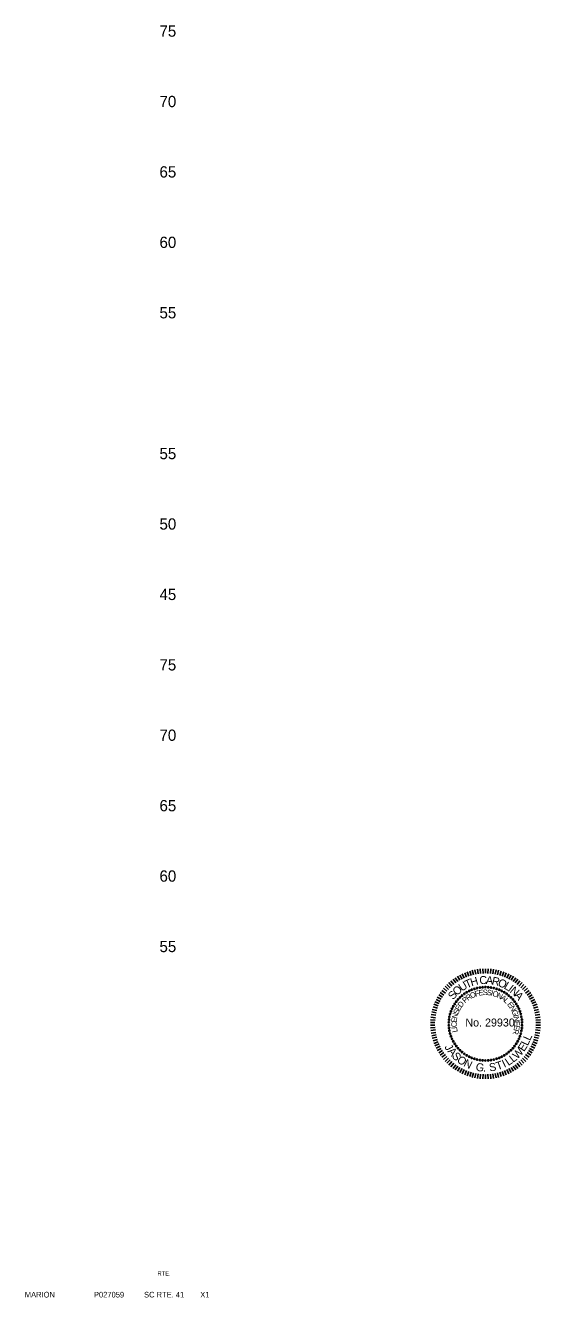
# Model space of a CAD drawing. Extents: x 952 to 1206, y 942 to 2399.
# Drawn here: x 1147.4 to 1184, y 1675.5 to 1765.8 of the extents above; entities that cross this region are included whole.
import ezdxf

# ---------------------------------------------------------------- set-up
doc = ezdxf.new("R2010")
doc.units = 0
for name, color, linetype in [('Default', 7, 'Continuous'), ('RD_SHT_TX', 7, 'Continuous'), ('RD_TX_PEShield', 7, 'Continuous'), ('RD_XS_TX_Elev_EX', 7, 'Continuous')]:
    doc.layers.add(name, color=color, linetype=linetype)

# ---------------------------------------------------------------- blocks, each defined once
blk = doc.blocks.new('STILLWELL')
at = {"layer": 'RD_TX_PEShield'}
for p, q in [((-10.28, 33.44), (-11.22, 36.57)), ((-8.61, 33.9), (-9.39, 37.07)), ((-6.92, 34.27), (-7.55, 37.48)), ((-5.21, 34.57), (-5.68, 37.8)), ((-3.49, 34.77), (-3.81, 38.03)), ((-1.76, 34.9), (-1.92, 38.16)), ((-0.03, 34.94), (-0.03, 38.21)), ((1.71, 34.9), (1.86, 38.16)), ((3.43, 34.77), (3.75, 38.03)), ((5.15, 34.57), (5.63, 37.8)), ((6.86, 34.27), (7.49, 37.48)), ((8.56, 33.9), (9.34, 37.07)), ((10.23, 33.44), (11.16, 36.57)), ((-23.81, 25.92), (-25.98, 28.37)), ((-22.49, 27.04), (-24.53, 29.59)), ((-21.11, 28.09), (-23.03, 30.73)), ((-19.68, 29.08), (-21.48, 31.81)), ((-18.21, 29.99), (-19.87, 32.81)), ((-16.7, 30.83), (-18.22, 33.73)), ((-15.14, 31.6), (-16.52, 34.56)), ((-13.55, 32.29), (-14.79, 35.32)), ((-11.93, 32.91), (-13.02, 35.99)), ((11.88, 32.91), (12.96, 35.99)), ((13.5, 32.29), (14.73, 35.32)), ((15.09, 31.6), (16.46, 34.56)), ((16.64, 30.83), (18.16, 33.73)), ((18.16, 29.99), (19.81, 32.81)), ((19.63, 29.08), (21.42, 31.81)), ((21.06, 28.09), (22.98, 30.73)), ((22.43, 27.04), (24.48, 29.59)), ((23.76, 25.92), (25.92, 28.37)), ((-31.38, 16.5), (-34.23, 18.09)), ((-30.5, 18), (-33.27, 19.72)), ((-29.55, 19.45), (-32.24, 21.3)), ((-28.53, 20.85), (-31.12, 22.83)), ((-27.44, 22.2), (-29.94, 24.31)), ((-26.29, 23.5), (-28.69, 25.72)), ((-25.08, 24.74), (-27.37, 27.08)), ((25.03, 24.74), (27.31, 27.08)), ((26.24, 23.5), (28.63, 25.72)), ((27.39, 22.2), (29.88, 24.31)), ((28.47, 20.85), (31.07, 22.83)), ((29.49, 19.45), (32.18, 21.3)), ((30.44, 18), (33.22, 19.72)), ((31.32, 16.5), (34.18, 18.09)), ((-34.64, 8.5), (-37.79, 9.35)), ((-34.14, 10.16), (-37.25, 11.17)), ((-33.57, 11.79), (-36.62, 12.95)), ((-32.91, 13.4), (-35.91, 14.7)), ((-32.18, 14.97), (-35.11, 16.42)), ((32.13, 14.97), (35.06, 16.42)), ((32.86, 13.4), (35.85, 14.7)), ((33.51, 11.79), (36.57, 12.95)), ((34.09, 10.16), (37.19, 11.17)), ((34.58, 8.5), (37.73, 9.35)), ((-35.89, -0.06), (-39.15, 0.02)), ((-35.8, 1.67), (-39.06, 1.91)), ((-35.64, 3.4), (-38.88, 3.79)), ((-35.39, 5.11), (-38.61, 5.66)), ((-35.05, 6.81), (-38.24, 7.52)), ((35, 6.81), (38.19, 7.52)), ((35.33, 5.11), (38.55, 5.66)), ((35.58, 3.4), (38.82, 3.79)), ((35.75, 1.67), (39.01, 1.91)), ((35.83, -0.06), (39.1, 0.02)), ((-35.89, -1.79), (-39.15, -1.87)), ((-35.8, -3.53), (-39.06, -3.76)), ((-35.64, -5.25), (-38.88, -5.65)), ((-35.39, -6.97), (-38.61, -7.52)), ((-35.05, -8.67), (-38.24, -9.37)), ((35, -8.67), (38.19, -9.37)), ((35.33, -6.97), (38.55, -7.52)), ((35.58, -5.25), (38.82, -5.65)), ((35.75, -3.53), (39.01, -3.76)), ((35.83, -1.79), (39.1, -1.87)), ((-34.64, -10.35), (-37.79, -11.21)), ((-34.14, -12.01), (-37.25, -13.02)), ((-33.57, -13.65), (-36.62, -14.81)), ((-32.91, -15.25), (-35.91, -16.56)), ((-32.18, -16.83), (-35.11, -18.27)), ((32.13, -16.83), (35.06, -18.27)), ((32.86, -15.25), (35.85, -16.56)), ((33.51, -13.65), (36.57, -14.81)), ((34.09, -12.01), (37.19, -13.02)), ((34.58, -10.35), (37.73, -11.21)), ((-31.38, -18.36), (-34.23, -19.95)), ((-30.5, -19.85), (-33.27, -21.58)), ((-29.55, -21.3), (-32.24, -23.16)), ((-28.53, -22.71), (-31.12, -24.69)), ((-27.44, -24.06), (-29.94, -26.16)), ((-26.29, -25.36), (-28.69, -27.58)), ((-25.08, -26.6), (-27.37, -28.93)), ((25.03, -26.6), (27.31, -28.93)), ((26.24, -25.36), (28.63, -27.58)), ((27.39, -24.06), (29.88, -26.16)), ((28.47, -22.71), (31.07, -24.69)), ((29.49, -21.3), (32.18, -23.16)), ((30.44, -19.85), (33.22, -21.58)), ((31.32, -18.36), (34.18, -19.95)), ((-23.81, -27.78), (-25.98, -30.22)), ((-22.49, -28.89), (-24.53, -31.44)), ((-21.11, -29.95), (-23.03, -32.59)), ((-19.68, -30.93), (-21.48, -33.66)), ((-18.21, -31.85), (-19.87, -34.66)), ((-16.7, -32.69), (-18.22, -35.58)), ((-15.14, -33.46), (-16.52, -36.42)), ((-13.55, -34.15), (-14.79, -37.18)), ((-11.93, -34.76), (-13.02, -37.85)), ((-10.28, -35.3), (-11.22, -38.43)), ((-8.61, -35.76), (-9.39, -38.93)), ((-6.92, -36.13), (-7.55, -39.34)), ((6.86, -36.13), (7.49, -39.34)), ((8.56, -35.76), (9.34, -38.93)), ((10.23, -35.3), (11.16, -38.43)), ((11.88, -34.76), (12.96, -37.85)), ((13.5, -34.15), (14.73, -37.18)), ((15.09, -33.46), (16.46, -36.42)), ((16.64, -32.69), (18.16, -35.58)), ((18.16, -31.85), (19.81, -34.66)), ((19.63, -30.93), (21.42, -33.66)), ((21.06, -29.95), (22.98, -32.59)), ((22.43, -28.89), (24.48, -31.44)), ((23.76, -27.78), (25.92, -30.22)), ((-5.21, -36.42), (-5.68, -39.65)), ((-3.49, -36.63), (-3.81, -39.88)), ((-1.76, -36.76), (-1.92, -40.02)), ((-0.03, -36.8), (-0.03, -40.06)), ((1.71, -36.76), (1.86, -40.02)), ((3.43, -36.63), (3.75, -39.88)), ((5.15, -36.42), (5.63, -39.65))]:
    blk.add_line(p, q, dxfattribs=at)
for centre in [(-18.09, 17.84), (-16.6, 19.17), (-15.01, 20.38), (-13.34, 21.46), (-11.59, 22.41), (-9.76, 23.23), (-7.89, 23.9), (-5.96, 24.43), (-4, 24.81), (-2.02, 25.04), (-0.03, 25.12), (1.97, 25.04), (3.95, 24.81), (5.91, 24.43), (7.83, 23.9), (9.71, 23.23), (11.53, 22.41), (13.28, 21.46), (14.96, 20.38), (16.54, 19.17), (18.03, 17.84), (-23.79, 9.73), (-22.91, 11.51), (-21.89, 13.23), (-20.74, 14.86), (-19.47, 16.4), (19.42, 16.4), (20.69, 14.86), (21.83, 13.23), (22.85, 11.51), (23.74, 9.73), (-26.05, 0.07), (-25.9, 2.06), (-25.6, 4.03), (-25.14, 5.97), (-24.54, 7.88), (24.48, 7.88), (25.09, 5.97), (25.54, 4.03), (25.85, 2.06), (26, 0.07), (-26.05, -1.93), (-25.9, -3.92), (-25.6, -5.89), (-25.14, -7.83), (25.09, -7.83), (25.54, -5.89), (25.85, -3.92), (26, -1.93), (-24.54, -9.73), (-23.79, -11.58), (-22.91, -13.37), (-21.89, -15.09), (-20.74, -16.72), (-19.47, -18.26), (19.42, -18.26), (20.69, -16.72), (21.83, -15.09), (22.85, -13.37), (23.74, -11.58), (24.48, -9.73), (-18.09, -19.69), (-16.6, -21.02), (-15.01, -22.23), (-13.34, -23.32), (-11.59, -24.27), (-9.76, -25.09), (-7.89, -25.76), (-5.96, -26.29), (-4, -26.67), (-2.02, -26.9), (-0.03, -26.97), (1.97, -26.9), (3.95, -26.67), (5.91, -26.29), (7.83, -25.76), (9.71, -25.09), (11.53, -24.27), (13.28, -23.32), (14.96, -22.23), (16.54, -21.02), (18.03, -19.69)]:
    blk.add_circle(centre, 0.49, dxfattribs=at)
for s, height, rotation, p in [('U', 5.68, 32.21524, (-16.89, 21.85)), ('T', 5.68, 23.50438, (-13.24, 24.14)), ('H', 5.68, 16.13567, (-9.92, 25.63)), ('C', 5.68, 4.07599, (-4.15, 27.11)), ('A', 5.68, 355.36513, (0.14, 27.41)), ('R', 5.68, 347.31877, (4.1, 27.11)), ('O', 5.68, 338.6079, (8.3, 26.16)), ('L', 5.68, 329.22596, (12.61, 24.44)), ('S', 5.68, 49.64355, (-22.94, 15.75)), ('O', 5.68, 41.59718, (-20.38, 18.79)), ('P', 3.92, 41.0022, (-14.52, 13.51)), ('R', 3.92, 33.30566, (-12.46, 15.32)), ('O', 3.92, 24.97351, (-9.98, 16.95)), ('F', 3.92, 15.99945, (-7.07, 18.28)), ('E', 3.92, 8.95111, (-4.65, 19)), ('S', 3.92, 1.25456, (-1.94, 19.44)), ('S', 3.92, 353.55802, (0.8, 19.51)), ('I', 3.92, 345.86148, (3.53, 19.22)), ('O', 3.92, 342.65826, (4.65, 18.99)), ('N', 3.92, 333.6842, (7.7, 18.01)), ('A', 3.92, 325.35205, (10.36, 16.69)), ('I', 5.68, 322.52176, (15.48, 22.79)), ('N', 5.68, 319.17294, (16.84, 21.84)), ('A', 5.68, 310.46208, (20.09, 19.02)), ('S', 3.92, 67.93066, (-19.49, 5.38)), ('E', 3.92, 60.23412, (-18.47, 7.93)), ('D', 3.92, 52.53758, (-17.12, 10.32)), ('L', 3.92, 317.65551, (12.63, 15.14)), ('E', 3.92, 308.03955, (15.14, 12.8)), ('N', 3.92, 300.34301, (16.84, 10.65)), ('C', 3.92, 92.29151, (-20.36, -3.21)), ('E', 3.92, 83.95936, (-20.47, -0.24)), ('N', 3.92, 76.26281, (-20.2, 2.49)), ('G', 3.92, 292.01086, (18.34, 8.08)), ('I', 3.92, 283.0368, (19.52, 5.11)), ('N', 3.92, 279.83358, (19.83, 4.01)), ('E', 3.92, 271.50143, (20.33, 1.08)), ('I', 3.92, 95.49473, (-20.2, -4.35)), ('L', 3.92, 101.90747, (-19.69, -6.58)), ('R', 3.92, 256.10834, (20.13, -4.4)), ('E', 3.92, 263.80489, (20.42, -1.67)), ('J', 5.68, 299.03302, (-29.35, -17.26)), ('W', 5.68, 47.05177, (22.62, -26.41)), ('E', 5.68, 56.4327, (27.3, -21.12)), ('L', 5.68, 65.09801, (29.98, -16.89)), ('L', 5.68, 65.09801, (31.58, -13.34)), ('A', 5.68, 310.58873, (-27.19, -20.61)), ('S', 5.68, 310.58873, (-24.3, -23.99)), ('O', 5.68, 321.00719, (-20.82, -27.39)), ('N', 5.68, 333.43256, (-16.05, -30.75)), ('T', 5.68, 18.90189, (8.5, -33.88)), ('I', 5.68, 25.39911, (13.3, -32.17)), ('L', 5.68, 34.06442, (16.21, -30.92)), ('L', 5.68, 37.67084, (19.57, -28.72)), ('G', 5.68, 352.2045, (-7.22, -34.2)), ('.', 5.68, 0.86982, (-1.8, -34.9)), ('S', 5.68, 8.08265, (2.93, -34.79))]:
    blk.add_text(s, height=height, rotation=rotation, dxfattribs=at).set_placement(p)
blk.add_text('No. 29930', height=5.685, dxfattribs=at).set_placement((-14.3, -2.84))

msp = doc.modelspace()

# ---------------------------------------------------------------- block references
at = {"layer": 'Default', "xscale": 0.1, "yscale": 0.10000000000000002}
msp.add_blockref('STILLWELL', (1180.075, 1695), dxfattribs=at)

# ---------------------------------------------------------------- texts
at = {"layer": 'RD_SHT_TX'}
for s, height, p in [('RTE.', 0.3, (1156.771, 1677.03)), ('MARION', 0.4, (1147.353, 1675.476)), ('P027059', 0.4, (1152.265, 1675.476)), ('SC RTE. 41', 0.4, (1155.822, 1675.476)), ('X1', 0.4, (1159.814, 1675.476))]:
    msp.add_text(s, height=height, dxfattribs=at).set_placement(p)
at = {"layer": 'RD_XS_TX_Elev_EX'}
for s, p in [('75', (1156.919, 1765)), ('70', (1156.919, 1760)), ('65', (1156.919, 1755)), ('60', (1156.919, 1750)), ('55', (1156.919, 1745)), ('55', (1156.919, 1735)), ('50', (1156.919, 1730)), ('45', (1156.919, 1725)), ('75', (1156.919, 1720)), ('70', (1156.919, 1715)), ('65', (1156.919, 1710)), ('60', (1156.919, 1705)), ('55', (1156.919, 1700))]:
    msp.add_text(s, height=0.8, dxfattribs=at).set_placement(p)

doc.saveas('drawing.dxf')
